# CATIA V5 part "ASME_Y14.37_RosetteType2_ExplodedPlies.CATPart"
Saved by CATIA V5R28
Part number: 333X3333-303
Revision: --
Nomenclature: ASME_Y14.37_RosetteType2
Bounding box of the stored display mesh (mm): x -183.371 to 149.821, y -702.181 to 651.972, z 2.54 to 93.98
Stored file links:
  C:\Users\jvl2147\Documents\ASME Y14.37\PartExamples\ASME_Y14.37_RosetteType2_ExplodedPlies.CATPart
  \\NW\Data\MSE-Composites\ASME Y14.37\ASME Y-14.37_COMPOSITES.CATMaterial
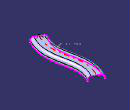
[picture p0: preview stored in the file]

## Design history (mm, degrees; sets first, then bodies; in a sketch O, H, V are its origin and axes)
AxisSystem1 "ROSETTE COORDINATE SYSTEM": origin (-72.9205, -637.9645, 93.98), X (0.5026, 0.8645, 0), Y (-0.8645, 0.5026, 0), Z (0, 0, 1)
CompParametersFeature1 "CATCoParametersFeatName": Value 0, Value 45, Value -45, Value 90
CompEOPGroupFeature1 "CATCoEOPGroupFeatName"
CompStacking1 "Stacking"
CompIsoThickAreasGroup1 "CATCoIsoThickAreasGroupFeatName": RefAddThickness 0
TTRSSet1
f4a2d38f3ddc11d3a929006094b99c4b_11 "CATTPSSet"
CompReviewTools1 "Review tools"
Set1 "CONSTRUCTION GEOMETRY"
  Set2 "CONSTRUCTION - LAMINATE REFERENCE SURFACE"
    Sketch1 on xy-plane, origin (0, 0, 0), H (1, 0, 0), V (0, 1, 0)
      spline S1 through (-79.505, -649.09) (21.2912, -260.3998) (-51.6257, 228.8061) (37.963, 602.845)
    Plane1: type Normal, Curve Sketch1, RefPoint vertex of Sketch1, Ratio 0
    Sketch2 on Plane1, origin (-464.3095, -417.3341, 0), H (-0.8566, 0.5159, 0), V (0, 0, 1)
      line L1 (-525.4052, 91.6386) -> (-373.0052, 91.6386)
      line L2 (-322.2052, 40.8386) -> (-322.2052, 0)
      line L3 (-576.2052, 0) -> (-576.2052, 40.8386)
      reference projected point E1 (-449.2052, 0) from vertex of Sketch1
      reference projected point E2 (-449.2052, 0) from vertex of Sketch1
      arc A1 centre (-373.0052, 40.8386) radius 50.8 from (-373.0052, 91.6386) to (-322.2052, 40.8386) cw
      arc A2 centre (-525.4052, 40.8386) radius 50.8 from (-576.2052, 40.8386) to (-525.4052, 91.6386) cw
      distance E1 L2 = 127
      distance E2 L3 = 127
      radius A1 = 50.8
      radius A2 = 50.8
      horizontal: L1 H
      vertical: L2 V, L3 V
      tangency: A1 L1, A1 L2, A2 L3, A2 L1
    Sweep1: type Unspec, Profile Sketch2, Guide Sketch1
  Set3 "CONSTRUCTION - PLIES EOPS"
    Plane2: type Normal, Curve Sketch1, RefPoint vertex of Sketch1, Ratio 0
    Plane3: type Normal, Curve Sketch1, RefPoint {point type OnCurve, Support Sketch1, Length 1118.262}, Ratio 0.99
    Plane4: type Normal, Curve Sketch1, Ratio 0.01
    Intersect1: ToIntersect1 Plane3, ToIntersect2 Sweep1
    Intersect2: ToIntersect1 Sweep1, ToIntersect2 Plane4
    Plane5: type Offset, RefPlane xy-plane, Offset 2.54
    Intersect3: ToIntersect1 Plane5, ToIntersect2 Join1
    Near1: MultiElement Intersect3, ReferenceElement edge of Sweep1
    Near2: MultiElement Intersect3, ReferenceElement edge of Sweep1
  Set4 "CONSTRUCTION - ROSETTE COORDINATE SYSTEM"
    Intersect4: ToIntersect1 Plane4, ToIntersect2 Project2
    Line1: type Tangency, RefPoint Intersect4, Curve Project2, Start 0, End 25.4
    Plane6: type Offset, RefPlane xy-plane, Offset 93.98
    Project1 "PROJECT": ToProject Sketch1, Support Join1, Direction xy-plane
  Set5 "CONSTRUCTION - ROSETTE TRANSFORMS"
    Line2 "Ply.1_Rosette_transfer_X": type Tangency, RefPoint {point type OnCurve, Support Project2, Length 288.56}, Curve Project2, Support Join1, Start 0, End 25.4
    Line3 "Ply.1_Rosette_transfer_X.Renamed": type Tangency, RefPoint {point type OnCurve, Support Project2, Length 536.186}, Curve Project2, Support Join1, Start 25.4, End 0
    Line4 "Ply.1_Rosette_transfer_X.Renamed": type Tangency, RefPoint {point type OnCurve, Support Project2, Length 783.62}, Curve Project2, Support Join1, Start 25.4, End 0
    Line5 "Ply.1_Rosette_transfer_X.Renamed": type Tangency, RefPoint {point type OnCurve, Support Project2, Length 1274.71}, Curve Project2, Support Join1, Start 25.4, End 0
    Line6 "Ply.1_Rosette_transfer_X.Renamed": type Tangency, RefPoint {point type OnCurve, Support Project2, Length 1017.245}, Curve Project2, Support Join1, Start 25.4, End 0
    AxisSystem2 "ROSETTE COORDINATE SYSTEM": origin (16.8931, -379.3831, 93.98), X (0.1242, 0.9923, 0), Y (-0.9923, 0.1242, 0), Z (0, 0, 1)
    AxisSystem3 "ROSETTE COORDINATE SYSTEM.Renamed": origin (7.1166, -132.8437, 93.98), X (-0.1632, 0.9866, 0), Y (-0.9866, -0.1632, 0), Z (0, 0, 1)
    AxisSystem4 "ROSETTE COORDINATE SYSTEM.Renamed1": origin (-38.9217, 110.2518, 93.98), X (-0.1571, 0.9876, 0), Y (-0.9876, -0.1571, 0), Z (0, 0, 1)
    AxisSystem5 "ROSETTE COORDINATE SYSTEM.Renamed2": origin (29.3229, 586.9432, 93.98), X (0.4677, 0.8839, 0), Y (-0.8839, 0.4677, 0), Z (0, 0, 1)
    AxisSystem6 "ROSETTE COORDINATE SYSTEM.Renamed3": origin (-47.995, 342.9553, 93.98), X (0.1137, 0.9935, 0), Y (-0.9935, 0.1137, 0), Z (0, 0, 1)
    Point1: type OnSurface, Support Join1, Length 362.156, Direction (-0.4364, -0.3881, 0.8118)
    Line7: type Normal, RefPoint Point1, RefSkin Join1, Start 254, End 0
  Plane7: type Offset, RefPlane YZ plane of AxisSystem2, Offset 0
  Circle1: type CtrRad, Start 0, End 180, Center {point type OnSurface, Support Join1, Length 336.531, Direction (0.5738, 0.5102, 0.6407)}, Support Join1, Radius 50.8, FirstDirection (1, 0, 0)
  CurvePar1: Offset Near1, Support Join1, Offset2 0, Offset1 50.8
Set6 "ENGINEERING GEOMETRY"
  Set7 "LAMINATE REFERENCE SURFACE"
    Join1 "LAMINATE REFERENCE SURFACE": Elements Sweep1
  Set8 "GUIDE CURVE - ZERO DEGREE ORIENTATION"
    Project2 "GUIDE CURVE - 0°": ToProject Sketch1, Support Plane6
Body1 (main body)
Body2 "-303"
  CompIsoThickAreasSolid1 "Area Solid.1": IsoAreasGroup CompIsoThickAreasGroup1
